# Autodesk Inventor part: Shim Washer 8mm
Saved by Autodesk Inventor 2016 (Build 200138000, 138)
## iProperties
Created: 2016-03
Part Number: Shim Washer 8mm
Material: Generic
Document SubType Name: Modeling
Designer: bongo_000
Density: 1 g/cm^3
Appearance: Default
Author: bongo_000
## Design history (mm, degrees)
feature "BOSS-EXTRUDE1"
body "Solid1"
